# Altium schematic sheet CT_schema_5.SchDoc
size 218 x 258 mm
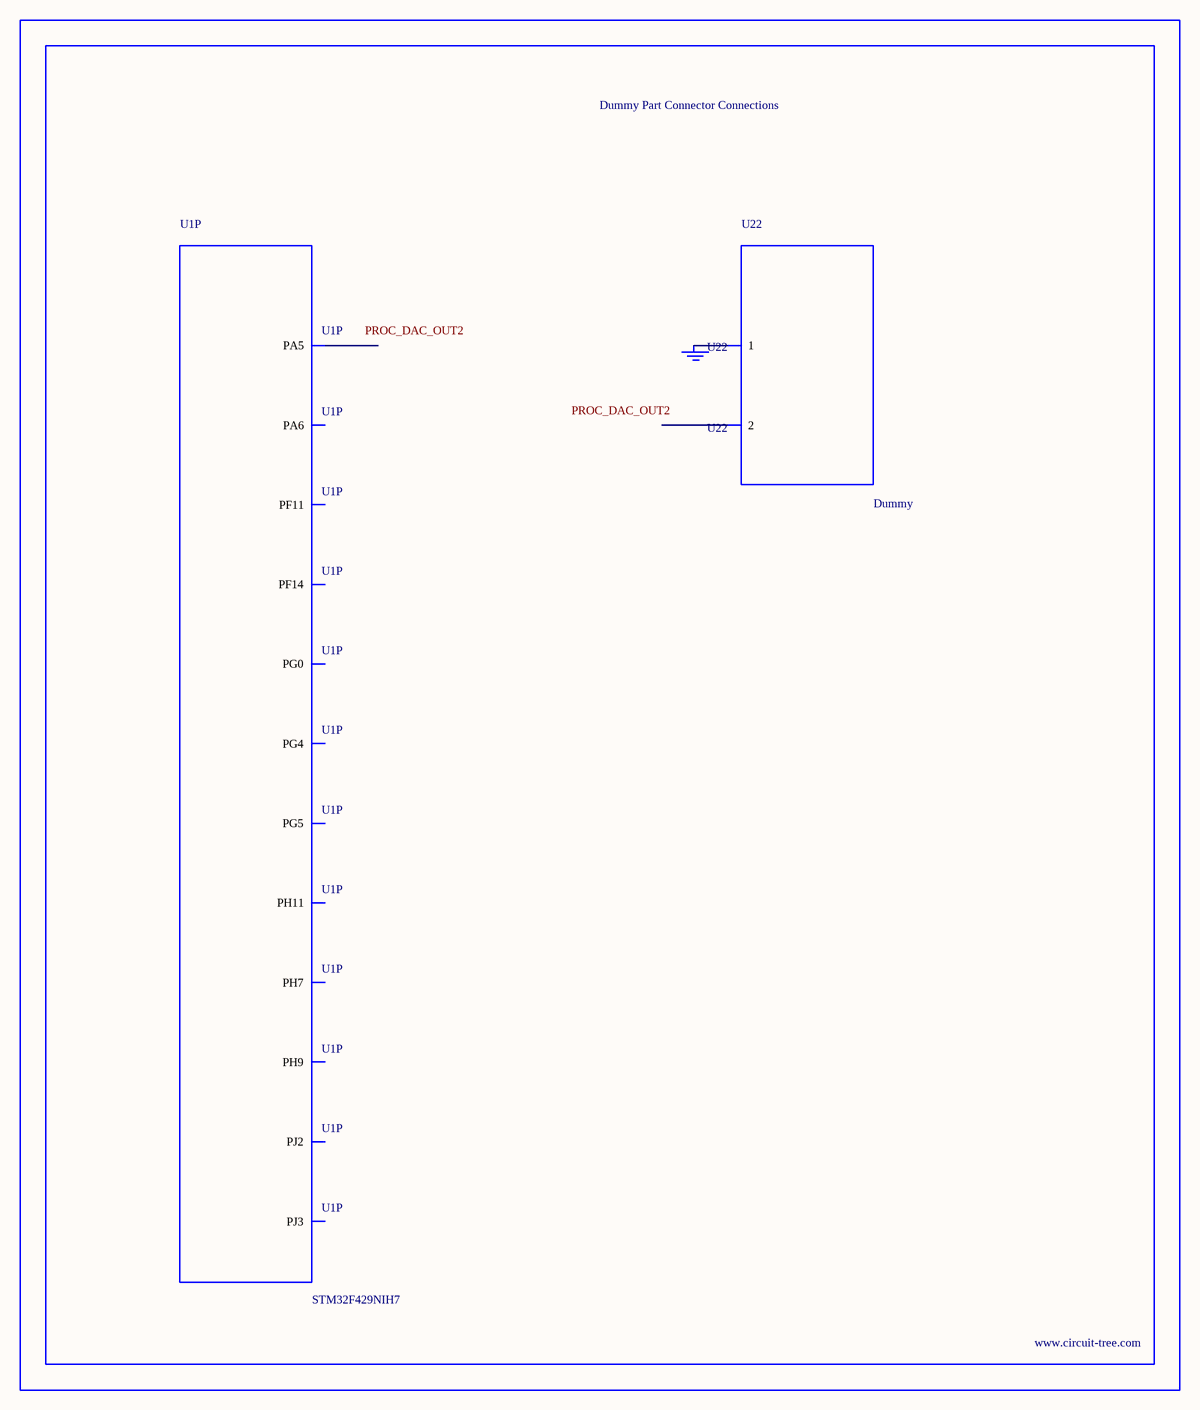
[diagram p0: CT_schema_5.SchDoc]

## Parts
BORDER4  (no value)
GND_INSTANCE_4_0  (no value)
U1  STM32F429NIH7  [TFBGA216]  (part P of 16)
U22  Dummy  [DUMMY_PACKAGE_318]

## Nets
NetGND_INSTANCE_4_0_0: GND_INSTANCE_4_0.0(GND) U22.1

Not connected (* = marked no-connect by the designer): U1 N7(PG0) N8(PJ3) N11(PG5) N12(PG4) N13(PH7) N14(PH9) N15(PH11) P3(PA6) P4(PA5) P6(PF14) P7(PJ2) P8(PF11); U22 2

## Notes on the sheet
- Labels drawn without touching a wire or pin: PROC_DAC_OUT2

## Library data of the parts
BORDER4 = BORDER_PAGE4
GND_INSTANCE_4_0 = GND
